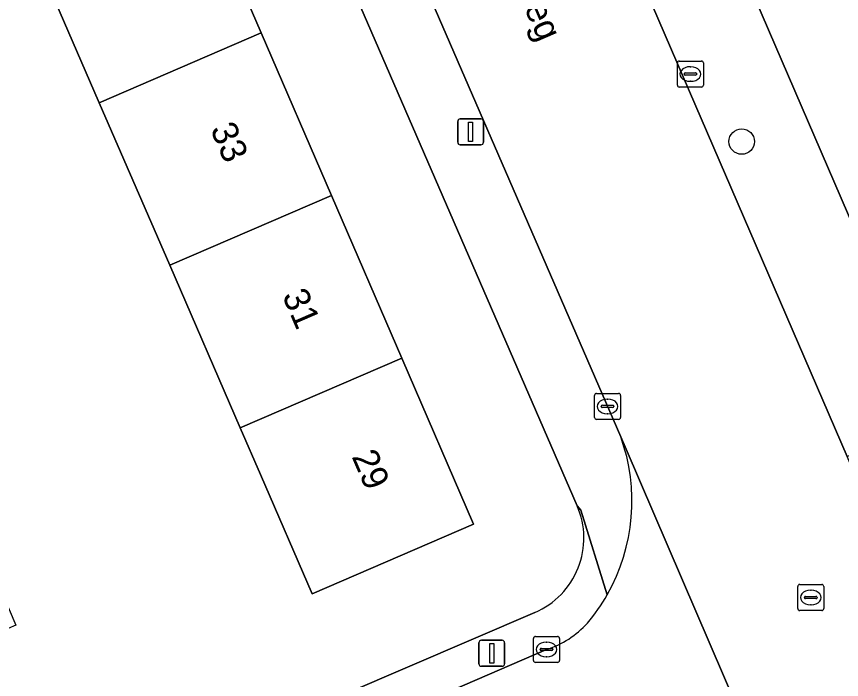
# Model space of a CAD drawing. Extents: x 159352 to 160617, y 385888 to 387323.
# Drawn here: x 159515.33 to 159547.05, y 386305.76 to 386331.24 of the extents above; entities that cross this region are included whole.
import ezdxf

# ---------------------------------------------------------------- set-up
doc = ezdxf.new("R2010")
doc.units = 0
for name, color, linetype in [('IMGEO_Boom', 7, 'Continuous'), ('IMGEO_Erf', 7, 'Continuous'), ('IMGEO_Kolk', 7, 'Continuous'), ('IMGEO_Lichtmast', 7, 'Continuous'), ('IMGEO_Openbare_ruimte_label', 7, 'Continuous'), ('IMGEO_Pand', 7, 'Continuous'), ('IMGEO_Pand_nummerreeks', 7, 'Continuous'), ('IMGEO_Rijbaan_lokaal_gesloten', 7, 'Continuous'), ('IMGEO_Rijbaan_lokaal_open', 7, 'Continuous'), ('IMGEO_Rioolput', 7, 'Continuous'), ('IMGEO_Voetpad_open', 7, 'Continuous')]:
    doc.layers.add(name, color=color, linetype=linetype)

msp = doc.modelspace()

# ---------------------------------------------------------------- linework, layer by layer
at = {"layer": 'IMGEO_Boom'}
msp.add_circle((159543.218, 386326.435), 0.489, dxfattribs=at)
at = {"layer": 'IMGEO_Erf'}
for points in [[(159536.89, 386312.44), (159519.208, 386353.167), (159516.654, 386358.401), (159511.384, 386368.121), (159507.312, 386374.992), (159506.211, 386376.719), (159502.854, 386382.067), (159499.095, 386378.359), (159500, 386377.441), (159503.35, 386374.044), (159500.475, 386371.208), (159498.348, 386369.111), (159496.222, 386367.014), (159494.096, 386364.918), (159491.969, 386362.821), (159489.842, 386360.724), (159487.667, 386358.631), (159483.403, 386362.885), (159469.132, 386348.816), (159458.454, 386342.171), (159488.971, 386293.139), (159489.075, 386292.971)], [(159532.833, 386357.179), (159552.875, 386310.756), (159572.078, 386319.046)], [(159522.039, 386336.87), (159524.742, 386330.62), (159527.445, 386324.369), (159530.148, 386318.119), (159532.91, 386311.732), (159526.706, 386309.05), (159524.716, 386313.638), (159523.936, 386315.436), (159521.226, 386321.684), (159518.517, 386327.931), (159515.807, 386334.178)], [(159502.096, 386331.814), (159504.69, 386325.876), (159507.068, 386326.901), (159508.491, 386323.6), (159509.894, 386320.344), (159507.516, 386319.319), (159510.109, 386313.381), (159512.487, 386314.406), (159513.909, 386311.105), (159515.313, 386307.849), (159512.935, 386306.824), (159515.861, 386300.009), (159535.268, 386308.34)]]:
    msp.add_lwpolyline(points, dxfattribs=at)
msp.add_arc((159534.036, 386311.198), 3.113, 293.3215, 23.5101, dxfattribs=at)
at = {"layer": 'IMGEO_Kolk'}
for p, q in [((159540.744, 386328.606), (159540.744, 386329.458)), ((159540.819, 386329.532), (159541.671, 386329.532)), ((159541.232, 386329.312), (159541.257, 386329.312)), ((159541.745, 386329.458), (159541.745, 386328.606)), ((159541.003, 386329.026), (159541.003, 386329.038)), ((159541.441, 386328.989), (159541.043, 386328.989)), ((159541.046, 386329.075), (159541.444, 386329.075)), ((159541.487, 386329.038), (159541.487, 386329.026)), ((159541.255, 386328.752), (159541.23, 386328.752)), ((159541.671, 386328.532), (159540.819, 386328.532)), ((159537.558, 386315.832), (159537.558, 386316.684)), ((159537.633, 386316.758), (159538.485, 386316.758)), ((159538.559, 386316.684), (159538.559, 386315.832)), ((159537.86, 386316.301), (159538.258, 386316.301)), ((159538.046, 386316.538), (159538.071, 386316.538)), ((159537.817, 386316.252), (159537.817, 386316.264)), ((159538.255, 386316.215), (159537.857, 386316.215)), ((159538.069, 386315.978), (159538.044, 386315.978)), ((159538.301, 386316.264), (159538.301, 386316.252)), ((159538.485, 386315.758), (159537.633, 386315.758)), ((159535.286, 386307.419), (159536.138, 386307.419)), ((159535.211, 386306.493), (159535.211, 386307.345)), ((159535.699, 386307.199), (159535.724, 386307.199)), ((159536.212, 386307.345), (159536.212, 386306.493)), ((159535.47, 386306.913), (159535.47, 386306.925)), ((159535.908, 386306.876), (159535.51, 386306.876)), ((159535.513, 386306.962), (159535.911, 386306.962)), ((159535.954, 386306.925), (159535.954, 386306.913)), ((159535.722, 386306.639), (159535.697, 386306.639)), ((159536.138, 386306.419), (159535.286, 386306.419))]:
    msp.add_line(p, q, dxfattribs=at)
for points in [[(159540.744, 386328.606), (159540.744, 386329.458)], [(159540.819, 386329.532), (159541.671, 386329.532)], [(159541.745, 386329.458), (159541.745, 386328.606)], [(159541.671, 386328.532), (159540.819, 386328.532)], [(159537.558, 386315.832), (159537.558, 386316.684)], [(159537.633, 386316.758), (159538.485, 386316.758)], [(159538.559, 386316.684), (159538.559, 386315.832)], [(159538.485, 386315.758), (159537.633, 386315.758)], [(159535.286, 386307.419), (159536.138, 386307.419)], [(159535.211, 386306.493), (159535.211, 386307.345)], [(159536.212, 386307.345), (159536.212, 386306.493)], [(159536.138, 386306.419), (159535.286, 386306.419)]]:
    msp.add_lwpolyline(points, dxfattribs=at)
for centre, radius, start, end in [((159540.821, 386329.456), 0.0765, 91.552, 178.448), ((159540.821, 386329.456), 0.0765, 91.552, 178.448), ((159541.669, 386329.456), 0.0765, 1.552, 88.448), ((159541.669, 386329.456), 0.0765, 1.552, 88.448), ((159541.043, 386329.035), 0.0403, 85.8775, 175.7526), ((159541.04, 386329.025), 0.0366, 178.938, 274.7102), ((159541.444, 386329.032), 0.043, 264.8664, 352.4533), ((159541.448, 386329.037), 0.0386, 1.7309, 96.639), ((159540.821, 386328.608), 0.0765, 181.552, 268.448), ((159540.821, 386328.608), 0.0765, 181.552, 268.448), ((159541.669, 386328.608), 0.0765, 271.552, 358.448), ((159541.669, 386328.608), 0.0765, 271.552, 358.448), ((159537.635, 386316.682), 0.0765, 91.552, 178.448), ((159537.635, 386316.682), 0.0765, 91.552, 178.448), ((159538.483, 386316.682), 0.0765, 1.552, 88.448), ((159538.483, 386316.682), 0.0765, 1.552, 88.448), ((159537.857, 386316.261), 0.0403, 85.8775, 175.7526), ((159538.262, 386316.263), 0.0386, 1.7309, 96.639), ((159537.854, 386316.251), 0.0366, 178.938, 274.7102), ((159538.258, 386316.258), 0.043, 264.8664, 352.4533), ((159537.635, 386315.834), 0.0765, 181.552, 268.448), ((159537.635, 386315.834), 0.0765, 181.552, 268.448), ((159538.483, 386315.834), 0.0765, 271.552, 358.448), ((159538.483, 386315.834), 0.0765, 271.552, 358.448), ((159535.288, 386307.343), 0.0765, 91.552, 178.448), ((159535.288, 386307.343), 0.0765, 91.552, 178.448), ((159536.136, 386307.343), 0.0765, 1.552, 88.448), ((159536.136, 386307.343), 0.0765, 1.552, 88.448), ((159535.51, 386306.922), 0.0403, 85.8775, 175.7526), ((159535.507, 386306.912), 0.0366, 178.938, 274.7102), ((159535.911, 386306.919), 0.043, 264.8664, 352.4533), ((159535.915, 386306.924), 0.0386, 1.7309, 96.639), ((159535.288, 386306.495), 0.0765, 181.552, 268.448), ((159535.288, 386306.495), 0.0765, 181.552, 268.448), ((159536.136, 386306.495), 0.0765, 271.552, 358.448), ((159536.136, 386306.495), 0.0765, 271.552, 358.448)]:
    msp.add_arc(centre, radius, start, end, dxfattribs=at)
for centre, major_axis, ratio, start_param, end_param in [((159541.231, 386329.032), (-0.387, 0.002), 0.722429, 4.712389, 7.853982), ((159541.256, 386329.032), (-0.39, 0.002), 0.717154, 1.570796, 4.712389), ((159538.045, 386316.258), (-0.387, 0.002), 0.722429, 4.712389, 7.853982), ((159538.07, 386316.258), (-0.39, 0.002), 0.717154, 1.570796, 4.712389), ((159535.698, 386306.919), (-0.387, 0.002), 0.722429, 4.712389, 7.853982), ((159535.723, 386306.919), (-0.39, 0.002), 0.717154, 1.570796, 4.712389)]:
    msp.add_ellipse(centre, major_axis=major_axis, ratio=ratio, start_param=start_param, end_param=end_param, dxfattribs=at)
at = {"layer": 'IMGEO_Lichtmast'}
for p, q in [((159532.299, 386326.411), (159532.299, 386327.211)), ((159532.299, 386327.211), (159532.299, 386326.411)), ((159532.399, 386327.311), (159533.189, 386327.311)), ((159533.189, 386327.311), (159532.399, 386327.311)), ((159533.289, 386327.211), (159533.289, 386326.411)), ((159533.289, 386326.411), (159533.289, 386327.211)), ((159533.189, 386326.311), (159532.399, 386326.311)), ((159532.399, 386326.311), (159533.189, 386326.311)), ((159533.112, 386306.372), (159533.112, 386307.172)), ((159533.112, 386307.172), (159533.112, 386306.372)), ((159533.212, 386307.272), (159534.002, 386307.272)), ((159534.002, 386307.272), (159533.212, 386307.272)), ((159534.102, 386307.172), (159534.102, 386306.372)), ((159534.102, 386306.372), (159534.102, 386307.172)), ((159534.002, 386306.272), (159533.212, 386306.272)), ((159533.212, 386306.272), (159534.002, 386306.272))]:
    msp.add_line(p, q, dxfattribs=at)
for points in [[(159532.719, 386327.186), (159532.869, 386327.186), (159532.869, 386326.436), (159532.719, 386326.436), (159532.719, 386327.186)], [(159533.532, 386307.147), (159533.682, 386307.147), (159533.682, 386306.397), (159533.532, 386306.397), (159533.532, 386307.147)]]:
    msp.add_lwpolyline(points, dxfattribs=at)
for centre, start, end in [((159532.399, 386327.211), 90, 180), ((159532.399, 386327.211), 90, 180), ((159533.189, 386327.211), 0, 90), ((159533.189, 386327.211), 360, 90), ((159532.399, 386326.411), 180, 270), ((159532.399, 386326.411), 180, 270), ((159533.189, 386326.411), 270, 0), ((159533.189, 386326.411), 270, 0), ((159533.212, 386307.172), 90, 180), ((159533.212, 386307.172), 90, 180), ((159534.002, 386307.172), 0, 90), ((159534.002, 386307.172), 360, 90), ((159533.212, 386306.372), 180, 270), ((159533.212, 386306.372), 180, 270), ((159534.002, 386306.372), 270, 0), ((159534.002, 386306.372), 270, 0)]:
    msp.add_arc(centre, 0.1, start, end, dxfattribs=at)
at = {"layer": 'IMGEO_Pand'}
for points in [[(159524.742, 386330.62), (159522.039, 386336.87), (159515.807, 386334.178), (159518.517, 386327.931)], [(159527.445, 386324.369), (159524.742, 386330.62), (159518.517, 386327.931), (159521.226, 386321.684)], [(159530.148, 386318.119), (159527.445, 386324.369), (159521.226, 386321.684), (159523.936, 386315.436)], [(159523.936, 386315.436), (159524.716, 386313.638), (159526.706, 386309.05), (159532.91, 386311.732), (159530.148, 386318.119)]]:
    msp.add_lwpolyline(points, close=True, dxfattribs=at)
at = {"layer": 'IMGEO_Rijbaan_lokaal_gesloten'}
for points in [[(159570.042, 386261.524), (159567.886, 386266.536), (159551.394, 386304.776), (159550.003, 386308.002), (159549.323, 386309.577), (159548.845, 386310.685), (159547.269, 386314.331), (159527.379, 386360.366), (159525.194, 386365.458), (159515.604, 386381.536), (159500.36, 386405.492), (159500, 386406.055), (159471.301, 386450.928)], [(159528.006, 386339.414), (159538.567, 386315.088), (159538.773, 386314.614), (159545.199, 386299.697), (159555.665, 386275.434), (159565.922, 386251.602), (159566.795, 386249.573), (159572.932, 386235.406)]]:
    msp.add_lwpolyline(points, dxfattribs=at)
at = {"layer": 'IMGEO_Rijbaan_lokaal_open'}
for points in [[(159545.199, 386299.697), (159538.773, 386314.614), (159538.567, 386315.088)], [(159535.708, 386306.916), (159522.591, 386301.241), (159502.565, 386292.66), (159500, 386291.615), (159494.624, 386289.424)]]:
    msp.add_lwpolyline(points, dxfattribs=at)
for centre, radius, start, end in [((159531.742, 386312.618), 7.258, 330.2872, 19.898), ((159531.773, 386312.597), 7.221, 319.7705, 330.3092), ((159534.616, 386310.343), 3.597, 287.6757, 317.9268)]:
    msp.add_arc(centre, radius, start, end, dxfattribs=at)
at = {"layer": 'IMGEO_Rioolput'}
for p, q in [((159545.373, 386308.489), (159545.373, 386309.341)), ((159545.448, 386309.415), (159546.3, 386309.415)), ((159546.374, 386309.341), (159546.374, 386308.489)), ((159545.861, 386309.195), (159545.886, 386309.195)), ((159545.632, 386308.909), (159545.632, 386308.921)), ((159546.07, 386308.872), (159545.672, 386308.872)), ((159545.675, 386308.958), (159546.073, 386308.958)), ((159546.116, 386308.921), (159546.116, 386308.909)), ((159546.3, 386308.415), (159545.448, 386308.415)), ((159545.884, 386308.635), (159545.859, 386308.635))]:
    msp.add_line(p, q, dxfattribs=at)
for points in [[(159545.373, 386308.489), (159545.373, 386309.341)], [(159545.448, 386309.415), (159546.3, 386309.415)], [(159546.374, 386309.341), (159546.374, 386308.489)], [(159546.3, 386308.415), (159545.448, 386308.415)]]:
    msp.add_lwpolyline(points, dxfattribs=at)
for centre, radius, start, end in [((159545.45, 386309.339), 0.0765, 91.552, 178.448), ((159545.45, 386309.339), 0.0765, 91.552, 178.448), ((159546.298, 386309.339), 0.0765, 1.552, 88.448), ((159546.298, 386309.339), 0.0765, 1.552, 88.448), ((159545.672, 386308.918), 0.0403, 85.8775, 175.7526), ((159545.669, 386308.908), 0.0366, 178.938, 274.7102), ((159546.073, 386308.915), 0.043, 264.8664, 352.4533), ((159546.077, 386308.92), 0.0386, 1.7309, 96.639), ((159545.45, 386308.491), 0.0765, 181.552, 268.448), ((159545.45, 386308.491), 0.0765, 181.552, 268.448), ((159546.298, 386308.491), 0.0765, 271.552, 358.448), ((159546.298, 386308.491), 0.0765, 271.552, 358.448)]:
    msp.add_arc(centre, radius, start, end, dxfattribs=at)
for centre, major_axis, ratio, start_param, end_param in [((159545.86, 386308.915), (-0.387, 0.002), 0.722429, 4.712389, 7.853982), ((159545.885, 386308.915), (-0.39, 0.002), 0.717154, 1.570796, 4.712389)]:
    msp.add_ellipse(centre, major_axis=major_axis, ratio=ratio, start_param=start_param, end_param=end_param, dxfattribs=at)
at = {"layer": 'IMGEO_Voetpad_open'}
for points in [[(159553.272, 386309.836), (159552.875, 386310.756), (159532.833, 386357.179), (159530.576, 386362.156), (159530.608, 386362.272), (159528.864, 386366.324), (159528.854, 386366.326), (159526.561, 386371.723)], [(159515.356, 386366.345), (159514.085, 386368.672), (159513.621, 386369.485), (159511.384, 386368.121), (159516.654, 386358.401), (159519.208, 386353.167), (159536.89, 386312.44), (159537.038, 386312.275), (159538.046, 386309.02)], [(159538.567, 386315.088), (159528.006, 386339.414), (159523.869, 386348.954), (159522.497, 386352.051), (159521.044, 386355.208), (159520.063, 386357.166), (159518.981, 386359.293), (159518, 386361.321), (159516.578, 386364.138), (159515.356, 386366.345)], [(159525.008, 386366.09), (159525.194, 386365.458), (159527.379, 386360.366), (159547.269, 386314.331), (159547.528, 386314.443), (159548.483, 386314.854), (159550.054, 386311.206), (159549.099, 386310.795), (159548.845, 386310.685), (159549.323, 386309.577), (159550.003, 386308.002), (159550.259, 386308.112), (159551.214, 386308.525), (159552.608, 386305.301), (159551.653, 386304.888), (159551.394, 386304.776), (159567.886, 386266.536), (159570.042, 386261.524)], [(159538.046, 386309.02), (159537.038, 386312.275), (159536.89, 386312.44)], [(159535.268, 386308.34), (159515.861, 386300.009), (159514.684, 386299.503), (159498.741, 386292.659), (159495.124, 386291.106)], [(159522.591, 386301.241), (159535.708, 386306.916)]]:
    msp.add_lwpolyline(points, dxfattribs=at)
for centre, radius, start, end in [((159531.742, 386312.618), 7.258, 330.2872, 19.898), ((159534.036, 386311.198), 3.113, 293.3215, 23.5101), ((159531.773, 386312.597), 7.221, 319.7705, 330.3092), ((159534.616, 386310.343), 3.597, 287.6757, 317.9268)]:
    msp.add_arc(centre, radius, start, end, dxfattribs=at)

# ---------------------------------------------------------------- texts
at = {"layer": 'IMGEO_Openbare_ruimte_label'}
msp.add_text('Jacob van Campenweg', height=1, rotation=293.462, dxfattribs=at).set_placement((159529.87, 386343.037))
at = {"layer": 'IMGEO_Pand_nummerreeks'}
for s, p in [('33', (159522.772, 386326.912)), ('31', (159525.536, 386320.519)), ('29', (159528.211, 386314.334))]:
    msp.add_text(s, height=1, rotation=293.386, dxfattribs=at).set_placement(p)

doc.saveas('drawing.dxf')
